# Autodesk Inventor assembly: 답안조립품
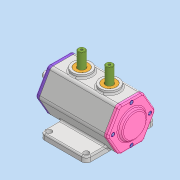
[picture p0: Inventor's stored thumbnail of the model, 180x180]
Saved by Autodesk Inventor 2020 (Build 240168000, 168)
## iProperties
Created: 2021-06
Part Number: 답안조립품
Document SubType Name: Assembly
Designer: MIRAE
Author: MIRAE
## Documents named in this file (11)
- C:\Users\MIRAE\Desktop\710606V1011\답안조립품.iam
- C:\Users\MIRAE\Desktop\710606V1011\본체.ipt
- C:\Users\MIRAE\Desktop\710606V1011\뒷커버.ipt
- C:\Users\MIRAE\Desktop\710606V1011\앞커버.ipt
- C:\Users\MIRAE\Desktop\710606V1011\베어링 6302.ipt
- C:\Users\MIRAE\Desktop\710606V1011\볼트 M4.ipt
- C:\Users\MIRAE\Desktop\710606V1011\편심축.ipt
- C:\Users\MIRAE\Desktop\710606V1011\베어링 6203.ipt
- C:\Users\MIRAE\Desktop\710606V1011\부시.ipt
- C:\Users\MIRAE\Desktop\710606V1011\오일실.ipt
- C:\Users\MIRAE\Desktop\710606V1011\슬라이더.ipt
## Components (10 placed, 3 different names)
1. 7-베어링 6203:1
2. 8-오일실:1
3. 9-M4-소켓머리:1
4. 9-M4-소켓머리:2
5. 9-M4-소켓머리:3
6. 9-M4-소켓머리:4
7. 9-M4-소켓머리:5
8. 9-M4-소켓머리:6
9. 9-M4-소켓머리:7
10. 9-M4-소켓머리:8
